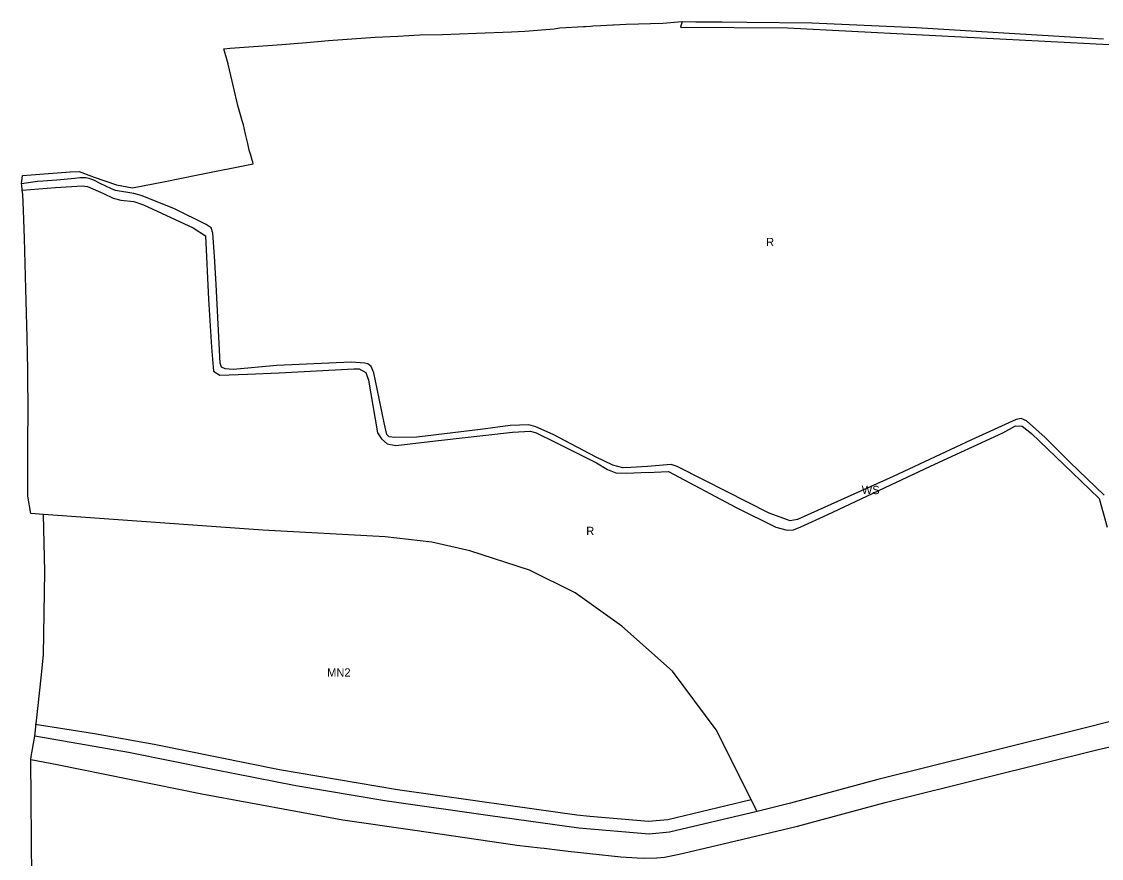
# Model space of a CAD drawing. Extents: x 7435758 to 7439981, y 5550649 to 5554049.
# Drawn here: x 7435758 to 7436433, y 5551221 to 5551745 of the extents above; entities that cross this region are included whole.
import ezdxf

# ---------------------------------------------------------------- set-up
doc = ezdxf.new("R2010")
doc.units = 0
for name, color, linetype in [('linie_rozgraniczające', 7, 'Continuous'), ('linie_zabudowy_nieprzekraczalne', 7, 'Continuous'), ('oznaczenia_przeznaczen', 7, 'Continuous')]:
    doc.layers.add(name, color=color, linetype=linetype)

msp = doc.modelspace()

# ---------------------------------------------------------------- linework, layer by layer
at = {"layer": 'linie_rozgraniczające'}
for p, q in [((7436072.6, 5551738.78), (7436091.05, 5551740.2)), ((7436091.05, 5551740.2), (7436094.63, 5551740.84)), ((7436094.63, 5551740.84), (7436109.31, 5551741.59)), ((7436109.31, 5551741.59), (7436109.85, 5551741.64)), ((7436109.85, 5551741.64), (7436110.7, 5551741.72)), ((7436110.7, 5551741.72), (7436113.71, 5551741.79)), ((7436113.71, 5551741.79), (7436115.16, 5551742.08)), ((7436115.16, 5551742.08), (7436120.21, 5551742.35)), ((7436120.21, 5551742.35), (7436127.76, 5551742.75)), ((7436127.76, 5551742.75), (7436128.08, 5551742.77)), ((7436128.08, 5551742.77), (7436136.04, 5551743.06)), ((7436136.04, 5551743.06), (7436159.04, 5551743.84)), ((7436159.04, 5551743.84), (7436171, 5551744.73)), ((7436171, 5551744.73), (7436169.95, 5551741.22)), ((7436169.95, 5551741.22), (7436236.93, 5551740.74)), ((7436171, 5551744.73), (7436179.6, 5551744.59)), ((7436179.6, 5551744.59), (7436181.46, 5551744.59)), ((7436181.46, 5551744.59), (7436196.17, 5551744.67)), ((7436196.17, 5551744.67), (7436211.63, 5551744.29)), ((7436211.63, 5551744.29), (7436252.22, 5551744.01)), ((7436236.93, 5551740.74), (7436438.25, 5551730.35)), ((7436252.22, 5551744.01), (7436317.65, 5551741.01)), ((7436317.65, 5551741.01), (7436375.57, 5551737.48)), ((7435949.83, 5551732.98), (7435964.39, 5551733.98)), ((7435964.39, 5551733.98), (7435979.14, 5551735.01)), ((7435979.14, 5551735.01), (7435993.33, 5551735.68)), ((7435993.33, 5551735.68), (7436007.09, 5551736.51)), ((7436007.09, 5551736.51), (7436021.2, 5551736.69)), ((7436021.2, 5551736.69), (7436042.47, 5551737.55)), ((7436042.47, 5551737.55), (7436064.31, 5551738.43)), ((7436064.31, 5551738.43), (7436072.6, 5551738.78)), ((7436375.57, 5551737.48), (7436434.62, 5551733.86)), ((7435884.33, 5551727.73), (7435888.36, 5551728.18)), ((7435887.16, 5551718.23), (7435884.33, 5551727.73)), ((7435888.36, 5551728.18), (7435900.04, 5551728.97)), ((7435900.04, 5551728.97), (7435920.75, 5551730.39)), ((7435920.75, 5551730.39), (7435936.03, 5551731.65)), ((7435936.03, 5551731.65), (7435949.83, 5551732.98)), ((7435887.2, 5551718.12), (7435887.16, 5551718.23)), ((7435890.47, 5551704), (7435887.2, 5551718.12)), ((7435893.21, 5551692.19), (7435890.47, 5551704)), ((7435895.24, 5551685.05), (7435893.21, 5551692.19)), ((7435895.94, 5551682.6), (7435895.24, 5551685.05)), ((7435896.63, 5551680.15), (7435895.94, 5551682.6)), ((7435897.99, 5551674.34), (7435896.63, 5551680.15)), ((7435899.35, 5551668.53), (7435897.99, 5551674.34)), ((7435899.85, 5551666.39), (7435899.35, 5551668.53)), ((7435900.35, 5551664.24), (7435899.85, 5551666.39)), ((7435901.24, 5551661.21), (7435900.35, 5551664.24)), ((7435902.14, 5551658.18), (7435901.24, 5551661.21)), ((7435868.1, 5551648.84), (7435902.76, 5551655.75)), ((7435902.45, 5551656.97), (7435902.14, 5551658.18)), ((7435902.76, 5551655.75), (7435902.45, 5551656.97)), ((7435758, 5551644.9), (7435758.49, 5551648.43)), ((7435758.49, 5551648.43), (7435788.37, 5551650.69)), ((7435779.88, 5551645.64), (7435771.19, 5551645.01)), ((7435791.24, 5551646.61), (7435779.88, 5551645.64)), ((7435788.37, 5551650.69), (7435793.96, 5551650.98)), ((7435794.38, 5551646.99), (7435791.24, 5551646.61)), ((7435793.96, 5551650.98), (7435803.21, 5551647.36)), ((7435796.84, 5551647.11), (7435794.38, 5551646.99)), ((7435798.19, 5551646.94), (7435796.84, 5551647.11)), ((7435800.14, 5551646.67), (7435798.19, 5551646.94)), ((7435803.2, 5551645.66), (7435800.14, 5551646.67)), ((7435807.12, 5551643.49), (7435803.2, 5551645.66)), ((7435803.21, 5551647.36), (7435817.37, 5551642.66)), ((7435847.75, 5551644.78), (7435868.1, 5551648.84)), ((7435767.94, 5551644.67), (7435757.92, 5551643.27)), ((7435757.92, 5551643.27), (7435757.94, 5551643.65)), ((7435757.99, 5551642.39), (7435757.92, 5551643.27)), ((7435757.94, 5551643.65), (7435758, 5551644.9)), ((7435758.21, 5551639.4), (7435757.99, 5551642.39)), ((7435758.21, 5551639.4), (7435779.15, 5551640.93)), ((7435758.23, 5551639.18), (7435758.21, 5551639.4)), ((7435758.61, 5551636.84), (7435758.23, 5551639.18)), ((7435771.19, 5551645.01), (7435767.94, 5551644.67)), ((7435779.15, 5551640.93), (7435795.82, 5551642.05)), ((7435795.82, 5551642.05), (7435799.23, 5551641.56)), ((7435799.23, 5551641.56), (7435809.09, 5551637.31)), ((7435814.16, 5551640.14), (7435807.12, 5551643.49)), ((7435816.72, 5551639.15), (7435814.16, 5551640.14)), ((7435828.03, 5551637.18), (7435816.72, 5551639.15)), ((7435817.37, 5551642.66), (7435827.37, 5551640.72)), ((7435827.37, 5551640.72), (7435847.75, 5551644.78)), ((7435759.17, 5551626.65), (7435758.61, 5551636.84)), ((7435809.09, 5551637.31), (7435815.11, 5551634.41)), ((7435815.11, 5551634.41), (7435819.95, 5551632.97)), ((7435819.95, 5551632.97), (7435828.02, 5551632.29)), ((7435828.02, 5551632.29), (7435834.26, 5551630.16)), ((7435830.38, 5551636.51), (7435828.03, 5551637.18)), ((7435833.41, 5551635.84), (7435830.38, 5551636.51)), ((7435853.6, 5551627.74), (7435833.41, 5551635.84)), ((7435759.83, 5551609.39), (7435759.17, 5551626.65)), ((7435834.26, 5551630.16), (7435865.27, 5551615.76)), ((7435873.35, 5551617.92), (7435853.6, 5551627.74)), ((7435865.27, 5551615.76), (7435872.89, 5551610.67)), ((7435876.46, 5551615.78), (7435873.35, 5551617.92)), ((7435877.47, 5551612.43), (7435876.46, 5551615.78)), ((7435878.68, 5551598.14), (7435877.47, 5551612.43)), ((7435760.47, 5551577.65), (7435759.83, 5551609.39)), ((7435872.89, 5551610.67), (7435874.87, 5551571.09)), ((7435879.53, 5551580.33), (7435878.68, 5551598.14)), ((7435882.15, 5551531.1), (7435879.53, 5551580.33)), ((7435761.45, 5551547.11), (7435760.47, 5551577.65)), ((7435874.87, 5551571.09), (7435876.72, 5551541.12)), ((7435761.87, 5551527.04), (7435761.45, 5551547.11)), ((7435876.72, 5551541.12), (7435877.96, 5551526.09)), ((7435882.88, 5551528.61), (7435882.15, 5551531.1)), ((7435964.08, 5551531.85), (7435917.66, 5551529.65)), ((7435972.53, 5551531.18), (7435964.08, 5551531.85)), ((7435974.44, 5551530.63), (7435972.53, 5551531.18)), ((7435761.96, 5551498.45), (7435761.87, 5551527.04)), ((7435877.96, 5551526.09), (7435881.95, 5551523.61)), ((7435881.95, 5551523.61), (7435899.28, 5551524.25)), ((7435885.31, 5551527.58), (7435882.88, 5551528.61)), ((7435890.23, 5551527.15), (7435885.31, 5551527.58)), ((7435917.66, 5551529.65), (7435890.23, 5551527.15)), ((7435899.28, 5551524.25), (7435919.1, 5551525.18)), ((7435919.1, 5551525.18), (7435965.63, 5551527.64)), ((7435965.63, 5551527.64), (7435969.03, 5551527.65)), ((7435969.03, 5551527.65), (7435973.27, 5551525.31)), ((7435973.27, 5551525.31), (7435974.98, 5551520.47)), ((7435976.64, 5551529.09), (7435974.44, 5551530.63)), ((7435978.18, 5551525.13), (7435976.64, 5551529.09)), ((7435980.34, 5551515.16), (7435978.18, 5551525.13)), ((7435974.98, 5551520.47), (7435980.58, 5551487.64)), ((7435984.6, 5551493.84), (7435980.34, 5551515.16)), ((7435761.89, 5551484.88), (7435761.96, 5551498.45)), ((7435986.28, 5551486.61), (7435984.6, 5551493.84)), ((7436063.61, 5551492.14), (7436044.99, 5551489.56)), ((7436075.16, 5551492.61), (7436063.61, 5551492.14)), ((7436079.48, 5551491.4), (7436075.16, 5551492.61)), ((7436090.49, 5551486.44), (7436079.48, 5551491.4)), ((7436379.97, 5551495.99), (7436352.08, 5551483.23)), ((7436371.76, 5551487.67), (7436379.51, 5551492.01)), ((7436379.51, 5551492.01), (7436383.79, 5551491.81)), ((7436383.22, 5551496.5), (7436379.97, 5551495.99)), ((7436386.42, 5551494.99), (7436383.22, 5551496.5)), ((7436383.79, 5551491.81), (7436389.63, 5551487.21)), ((7436398.16, 5551484.66), (7436386.42, 5551494.99)), ((7435761.89, 5551479.2), (7435761.89, 5551484.88)), ((7435980.58, 5551487.64), (7435983.13, 5551483.72)), ((7435983.13, 5551483.72), (7435986.65, 5551480.6)), ((7435987.85, 5551485.04), (7435986.28, 5551486.61)), ((7435991.39, 5551484.56), (7435987.85, 5551485.04)), ((7436005.08, 5551484.8), (7435991.39, 5551484.56)), ((7436044.99, 5551489.56), (7436005.08, 5551484.8)), ((7436018.61, 5551482.84), (7436065.04, 5551487.99)), ((7436065.04, 5551487.99), (7436076.32, 5551488.7)), ((7436076.32, 5551488.7), (7436079.76, 5551487.64)), ((7436079.76, 5551487.64), (7436091.69, 5551481.72)), ((7436116.95, 5551472.56), (7436090.49, 5551486.44)), ((7436326.35, 5551466.72), (7436371.76, 5551487.67)), ((7436389.63, 5551487.21), (7436415.01, 5551462.84)), ((7436413.62, 5551469.2), (7436398.16, 5551484.66)), ((7435761.89, 5551454.79), (7435761.89, 5551479.2)), ((7435986.65, 5551480.6), (7435992.1, 5551479.56)), ((7435992.1, 5551479.56), (7436018.61, 5551482.84)), ((7436091.69, 5551481.72), (7436117.61, 5551468.81)), ((7436352.08, 5551483.23), (7436302.99, 5551460.18)), ((7436127.72, 5551467.4), (7436116.95, 5551472.56)), ((7436117.61, 5551468.81), (7436124.31, 5551464.69)), ((7436124.31, 5551464.69), (7436129.67, 5551462.64)), ((7436134.07, 5551465.77), (7436127.72, 5551467.4)), ((7436138.96, 5551465.97), (7436134.07, 5551465.77)), ((7436149.5, 5551466.53), (7436138.96, 5551465.97)), ((7436164.28, 5551467.75), (7436149.5, 5551466.53)), ((7436153.66, 5551463.05), (7436162.45, 5551463.41)), ((7436162.45, 5551463.41), (7436204.97, 5551440.93)), ((7436167.98, 5551466.52), (7436164.28, 5551467.75)), ((7436184.8, 5551457.9), (7436167.98, 5551466.52)), ((7436261.84, 5551436.39), (7436326.35, 5551466.72)), ((7436435.07, 5551448.64), (7436413.62, 5551469.2)), ((7436129.67, 5551462.64), (7436136.22, 5551462.28)), ((7436136.22, 5551462.28), (7436145.38, 5551462.71)), ((7436145.38, 5551462.71), (7436153.66, 5551463.05)), ((7436225.48, 5551437.24), (7436184.8, 5551457.9)), ((7436302.99, 5551460.18), (7436268.17, 5551444.57)), ((7436415.01, 5551462.84), (7436432.01, 5551446.56)), ((7435761.76, 5551448.38), (7435761.89, 5551454.79)), ((7435761.75, 5551448.06), (7435761.76, 5551448.38)), ((7435763.6, 5551437.09), (7435761.75, 5551448.06)), ((7436268.17, 5551444.57), (7436243.24, 5551433.31)), ((7436432.01, 5551446.56), (7436436.88, 5551428.6)), ((7435763.64, 5551437.09), (7435763.6, 5551437.09)), ((7435771.55, 5551436.5), (7435763.64, 5551437.09)), ((7435772.41, 5551400.86), (7435771.55, 5551436.5)), ((7435908.88, 5551426.77), (7435771.55, 5551436.5)), ((7436204.97, 5551440.93), (7436229.61, 5551428.48)), ((7436236.33, 5551433.28), (7436225.48, 5551437.24)), ((7436245.31, 5551428.74), (7436261.84, 5551436.39)), ((7436238.74, 5551432.62), (7436236.33, 5551433.28)), ((7436243.24, 5551433.31), (7436238.74, 5551432.62)), ((7435985.28, 5551422.61), (7435908.88, 5551426.77)), ((7436229.61, 5551428.48), (7436236.85, 5551426.64)), ((7436236.85, 5551426.64), (7436240.73, 5551426.92)), ((7436240.73, 5551426.92), (7436245.31, 5551428.74)), ((7436014.45, 5551419.26), (7435985.28, 5551422.61)), ((7436038.27, 5551413.87), (7436014.45, 5551419.26)), ((7436075.51, 5551401.77), (7436038.27, 5551413.87)), ((7435771.69, 5551348.78), (7435772.41, 5551400.86)), ((7436104.23, 5551387.51), (7436075.51, 5551401.77)), ((7436133.43, 5551366.69), (7436104.23, 5551387.51)), ((7436164.98, 5551338.47), (7436133.43, 5551366.69)), ((7435770.15, 5551334.3), (7435771.69, 5551348.78)), ((7436192.32, 5551301.92), (7436164.98, 5551338.47)), ((7435766.25, 5551297.88), (7435770.15, 5551334.3)), ((7436452.23, 5551310.42), (7436426.71, 5551303.89)), ((7436218.05, 5551250.84), (7436192.32, 5551301.92)), ((7436426.71, 5551303.89), (7436358.09, 5551286.82)), ((7435763.94, 5551285.1), (7435766.25, 5551297.88)), ((7435824.87, 5551287.65), (7435766.25, 5551297.88)), ((7436430.38, 5551289.37), (7436459.7, 5551296.03)), ((7435878.67, 5551276.83), (7435824.87, 5551287.65)), ((7436361.62, 5551272.24), (7436430.38, 5551289.37)), ((7435763.61, 5551283.25), (7435763.94, 5551285.1)), ((7435764.25, 5551208.63), (7435763.61, 5551283.25)), ((7435763.61, 5551283.25), (7435780.07, 5551280.12)), ((7436358.09, 5551286.82), (7436293.52, 5551270.71)), ((7435780.07, 5551280.12), (7435870.74, 5551261.78)), ((7435929.51, 5551266.86), (7435878.67, 5551276.83)), ((7436293.52, 5551270.71), (7436238.85, 5551255.96)), ((7436297.98, 5551256.42), (7436361.62, 5551272.24)), ((7435870.74, 5551261.78), (7435958.83, 5551245.49)), ((7435985.14, 5551257.51), (7435929.51, 5551266.86)), ((7436051.09, 5551247.99), (7435985.14, 5551257.51)), ((7436238.85, 5551255.96), (7436218.05, 5551250.84)), ((7436243.31, 5551241.67), (7436297.98, 5551256.42)), ((7436106.37, 5551240.43), (7436051.09, 5551247.99)), ((7436218.05, 5551250.84), (7436163.13, 5551237.86)), ((7435958.83, 5551245.49), (7436003.98, 5551239.1)), ((7436150.36, 5551236.69), (7436106.37, 5551240.43)), ((7436192.29, 5551229.42), (7436243.31, 5551241.67)), ((7436003.98, 5551239.1), (7436066.46, 5551229.99)), ((7436163.13, 5551237.86), (7436150.36, 5551236.69)), ((7436066.46, 5551229.99), (7436067.62, 5551229.82)), ((7436067.62, 5551229.82), (7436082.25, 5551228.09)), ((7436082.25, 5551228.09), (7436084.72, 5551227.8)), ((7436084.72, 5551227.8), (7436094.52, 5551226.64)), ((7436169.13, 5551224.03), (7436192.29, 5551229.42)), ((7436094.52, 5551226.64), (7436099.81, 5551226.01)), ((7436099.81, 5551226.01), (7436113.3, 5551224.5)), ((7436113.3, 5551224.5), (7436132.65, 5551222.48)), ((7436132.65, 5551222.48), (7436143.02, 5551221.76)), ((7436143.02, 5551221.76), (7436147.79, 5551221.63)), ((7436147.79, 5551221.63), (7436155.28, 5551221.79)), ((7436155.28, 5551221.79), (7436160, 5551222.2)), ((7436160, 5551222.2), (7436169.13, 5551224.03))]:
    msp.add_line(p, q, dxfattribs=at)
at = {"layer": 'linie_zabudowy_nieprzekraczalne'}
msp.add_lwpolyline([(7435766.36, 5551305.41), (7435803.43, 5551299.58), (7435840.79, 5551292.83), (7435919.24, 5551277), (7435993.12, 5551264.56), (7436063.62, 5551254.48), (7436105.11, 5551248.68), (7436113.4, 5551247.93), (7436150.03, 5551244.68), (7436162.1, 5551245.83), (7436214.17, 5551258.38)], dxfattribs=at)

# ---------------------------------------------------------------- texts
at = {"layer": 'oznaczenia_przeznaczen'}
for s, p in [('R', (7436223.58, 5551604.3)), ('WS', (7436283.43, 5551449.23)), ('R', (7436111.1, 5551423.6)), ('MN2', (7435949.01, 5551335.1))]:
    msp.add_text(s, height=5.2, dxfattribs=at).set_placement(p)

doc.saveas('drawing.dxf')
